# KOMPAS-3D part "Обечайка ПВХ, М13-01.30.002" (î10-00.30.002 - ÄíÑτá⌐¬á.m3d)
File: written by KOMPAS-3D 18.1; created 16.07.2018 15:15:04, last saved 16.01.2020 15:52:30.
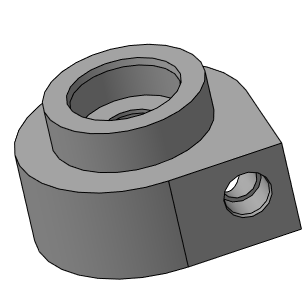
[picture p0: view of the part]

Document properties: Автор: Милов; Полное имя файла: D:\Magna\Магна Ins\Магна ins 10\М10-00.00.000\3Д\М10-00.30.002 - Обечайка.m3d

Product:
- Part/product: Обечайка ПВХ  | designation М13-01.30.002
    Масса: 0.766456
    Раздел спецификации: Детали
    Форматы листов документа: A4
    source file: ..\..\..\Магна ins 13\М13-01.00.000 ПВХ\Чертежи Компас\М13-01.30.002 - Обечайка.cdw, М10-00.30.002 - Обечайка.cdw
- Part/product: Обечайка  | designation М10-00.30.002
    Масса: 0.438641
  - Component [detail]: Труба 160 S=14,6 / FV PPR ф. "FV PLAST"  | Материал: Полипропилен  ГОСТ 26996-86 (density 900 kg/m3); Масса: 0.720263; Раздел спецификации: Прочие изделия; Примечание: м; source file: Труба 160 S=14,6 FV PPR ф. FV PLAST.m3d

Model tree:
1. Плоскость под углом:1
2. Смещенная плоскость:1
     Расстояние = 80
3. Эскиз:5  (with: Операция выдавливания:1)
4. Вырезать элемент выдавливания:4
     Расстояние 1 = 63
5. Фаска:1  (with: Операция выдавливания:1)  (labels: Полипропилен  ГОСТ 26996-86)
     Угол = 45; Длина 1 = 4; Длина 2 = 4
6. Эскиз:6
7. Операция выдавливания:1
     Расстояние 1 = 38; Расстояние 2 = 38
8. Вырезать элемент выдавливания:5
     Расстояние 2 = 30; Расстояние 1 = 20
9. Эскиз:9  (with: Операция выдавливания:1)
10. Элемент выдавливания:1
     Расстояние 2 = 5
11. Эскиз:11  (with: Операция выдавливания:1)
12. Элемент выдавливания:2  (with: Элемент выдавливания:1)
     Расстояние 1 = -22
13. Эскиз:12  (with: Операция выдавливания:1, Элемент выдавливания:2)
14. Элемент выдавливания:4
     Расстояние 1 = 36
15. Эскиз:14  (with: Элемент выдавливания:4)
16. Элемент выдавливания:5
     Расстояние 1 = 5
17. Эскиз:16  (with: Операция выдавливания:1)
18. Элемент выдавливания:6
     Расстояние 2 = 22
19. Эскиз:18  (with: Элемент выдавливания:6, Операция выдавливания:1)  (labels: Труба\Труба 32 PN10 S=2,9 FV PPR ф. "FV PLAST")
20. Элемент выдавливания:7
     Расстояние 2 = 56
21. Эскиз:20  (with: Элемент выдавливания:2)
22. Элемент выдавливания:8
     Расстояние 2 = 1
23. Фаска:5  (with: Элемент выдавливания:6, Эскиз:22, Элемент выдавливания:5)
     Угол = 15; Длина 1 = 3; Длина 2 = 0.803848
24. Элемент выдавливания:9  (with: Эскиз:24, Элемент выдавливания:2, Элемент выдавливания:8)
     Расстояние 1 = 17.5
25. Элемент выдавливания:11  (with: Эскиз:28, Элемент выдавливания:9, Фаска:6)
     Расстояние 2 = 5
26. Элемент выдавливания:13
     Расстояние 1 = 32
27. Эскиз:29  (with: Элемент выдавливания:2, Элемент выдавливания:11)
28. Элемент выдавливания:14
     Расстояние 2 = 1
29. Эскиз:30  (with: Элемент выдавливания:11)
30. Элемент выдавливания:15
     Расстояние 1 = 44
31. Фаска:8  (with: Элемент выдавливания:15, Эскиз:32, Элемент выдавливания:11)
     Угол = 15; Длина 1 = 5; Длина 2 = 1.33975
32. Элемент выдавливания:16
     Расстояние 2 = 10
33. Элемент выдавливания:21  (with: Элемент выдавливания:11, Эскиз:36)
     Расстояние 1 = 15.5
34. Элемент выдавливания:22
     Расстояние 1 = 3
35. Эскиз:37  (with: Операция выдавливания:1)
36. Элемент выдавливания:23
     Расстояние 2 = 21
37. Эскиз:38  (with: Элемент выдавливания:23)
38. Элемент выдавливания:24
     Расстояние 1 = 4
39. Условное изображение резьбы:1  (with: Элемент выдавливания:23, Элемент выдавливания:24)  (labels: M140x3; cil0_24705-2004 fine)
     Длина резьбы = 17; Шаг резьбы = 3; Номинальный диаметр резьбы = 140
40. Подгонка:1  (with: Элемент выдавливания:23)
41. Фаска:9  (with: Элемент выдавливания:23)
     Угол = 45; Длина 1 = 2.5; Длина 2 = 2.5
42. Эскиз:39  (with: Элемент выдавливания:14, Элемент выдавливания:11)
43. Элемент выдавливания:25  (with: Элемент выдавливания:22)
44. Фаска:11  (with: Элемент выдавливания:25)
     Угол = 45; Длина 1 = 2; Длина 2 = 2

Referenced files in D:\Magna\Магна Ins\Магна ins 10\М10-00.00.000\3Д\: Труба 160 S=14,6 FV PPR ф. FV PLAST.m3d, М10-00.30.000 - Обечайка.a3d
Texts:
  Body Specification ( left align )
  Body Specificaton ( centered )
